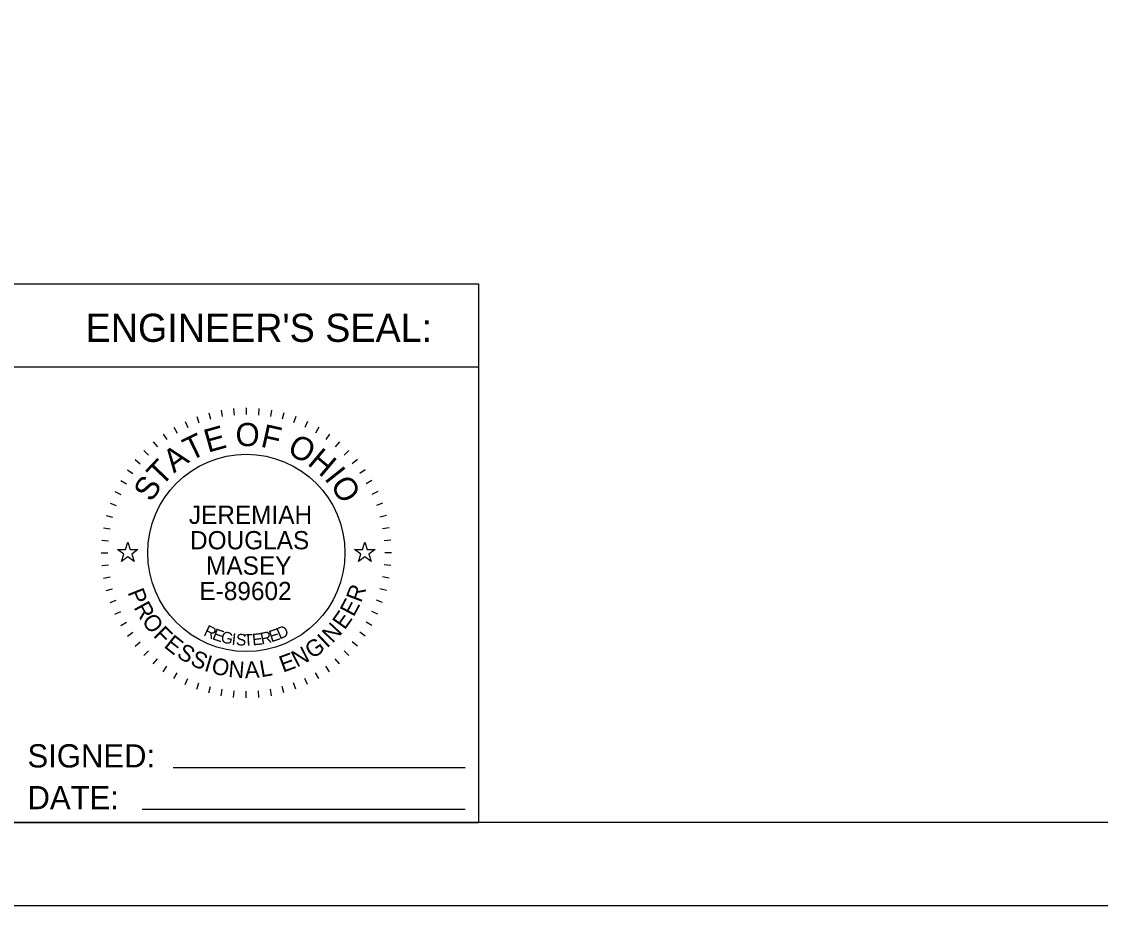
# Model space of a CAD drawing. Extents: x 0 to 36.5, y 0 to 25.3.
# Drawn here: x 23.3 to 29.81, y 0 to 5.33 of the extents above; entities that cross this region are included whole.
import ezdxf

# ---------------------------------------------------------------- set-up
doc = ezdxf.new("R2010")
doc.units = 0
for name, color, linetype in [('SH_Border', 7, 'Continuous'), ('SH_Cut_Line', 7, 'Continuous'), ('SH_Data', 7, 'Continuous'), ('SH_Text', 7, 'Continuous')]:
    doc.layers.add(name, color=color, linetype=linetype)

msp = doc.modelspace()

# ---------------------------------------------------------------- linework, layer by layer
at = {"layer": 'SH_Border'}
msp.add_lwpolyline([(1.5, 21.5), (33.5, 21.5), (33.5, 0.5), (1.5, 0.5)], close=True, dxfattribs=at)
at = {"layer": 'SH_Cut_Line'}
msp.add_lwpolyline([(0, 0), (34, 0), (34, 22), (0, 22)], close=True, dxfattribs=at)
at = {"layer": 'SH_Data'}
for p, q in [((23.2559, 3.75), (26.0559, 3.75)), ((23.2559, 3.25), (26.0559, 3.25)), ((24.5796, 2.9986), (24.5831, 2.9587)), ((24.6559, 3.0019), (24.6559, 2.9619)), ((24.7321, 2.9986), (24.7287, 2.9587)), ((24.3566, 2.9491), (24.3703, 2.9116)), ((24.4294, 2.9721), (24.4398, 2.9335)), ((24.5039, 2.9886), (24.5109, 2.9492)), ((24.8078, 2.9886), (24.8009, 2.9492)), ((24.8824, 2.9721), (24.872, 2.9335)), ((24.9552, 2.9491), (24.9415, 2.9116)), ((24.2184, 2.8847), (24.2384, 2.85)), ((24.2861, 2.9199), (24.303, 2.8837)), ((25.0257, 2.9199), (25.0088, 2.8837)), ((25.0934, 2.8847), (25.0734, 2.85)), ((24.154, 2.8437), (24.177, 2.8109)), ((25.1578, 2.8437), (25.1348, 2.8109)), ((24.0372, 2.7456), (24.0655, 2.7173)), ((24.0934, 2.7972), (24.1192, 2.7666)), ((25.2183, 2.7972), (25.1926, 2.7666)), ((25.2746, 2.7456), (25.2463, 2.7173)), ((23.9856, 2.6894), (24.0162, 2.6636)), ((25.3262, 2.6894), (25.2955, 2.6636)), ((23.9391, 2.6288), (23.9719, 2.6058)), ((25.3726, 2.6288), (25.3399, 2.6058)), ((23.8981, 2.5644), (23.9328, 2.5444)), ((25.4137, 2.5644), (25.379, 2.5444)), ((23.8629, 2.4967), (23.8991, 2.4798)), ((25.4489, 2.4967), (25.4127, 2.4798)), ((23.8337, 2.4262), (23.8712, 2.4125)), ((25.4781, 2.4262), (25.4405, 2.4125)), ((23.8107, 2.3534), (23.8493, 2.343)), ((25.5011, 2.3534), (25.4624, 2.343)), ((23.7942, 2.2789), (23.8336, 2.2719)), ((25.5176, 2.2789), (25.4782, 2.2719)), ((23.7842, 2.2032), (23.8241, 2.1997)), ((25.5276, 2.2032), (25.4877, 2.1997)), ((23.7809, 2.1269), (23.8209, 2.1269)), ((25.5309, 2.1269), (25.4909, 2.1269)), ((23.7842, 2.0507), (23.8241, 2.0541)), ((25.5276, 2.0507), (25.4877, 2.0541)), ((23.7942, 1.975), (23.8336, 1.9819)), ((25.5176, 1.975), (25.4782, 1.9819)), ((23.8107, 1.9004), (23.8493, 1.9108)), ((25.5011, 1.9004), (25.4624, 1.9108)), ((23.8337, 1.8276), (23.8712, 1.8413)), ((25.4781, 1.8276), (25.4405, 1.8413)), ((23.8629, 1.7571), (23.8991, 1.774)), ((25.4489, 1.7571), (25.4127, 1.774)), ((23.8981, 1.6894), (23.9328, 1.7094)), ((25.4137, 1.6894), (25.379, 1.7094)), ((23.9391, 1.625), (23.9719, 1.648)), ((25.3726, 1.625), (25.3399, 1.648)), ((23.9856, 1.5645), (24.0162, 1.5902)), ((25.3262, 1.5645), (25.2955, 1.5902)), ((24.0372, 1.5082), (24.0655, 1.5365)), ((25.2746, 1.5082), (25.2463, 1.5365)), ((24.0934, 1.4566), (24.1192, 1.4873)), ((24.154, 1.4102), (24.177, 1.4429)), ((25.1578, 1.4102), (25.1348, 1.4429)), ((25.2183, 1.4566), (25.1926, 1.4873)), ((24.2184, 1.3691), (24.2384, 1.4038)), ((24.2861, 1.3339), (24.303, 1.3701)), ((25.0257, 1.3339), (25.0088, 1.3701)), ((25.0934, 1.3691), (25.0734, 1.4038)), ((24.3566, 1.3047), (24.3703, 1.3423)), ((24.4294, 1.2817), (24.4398, 1.3204)), ((24.5039, 1.2652), (24.5109, 1.3046)), ((24.8078, 1.2652), (24.8009, 1.3046)), ((24.8824, 1.2817), (24.872, 1.3204)), ((24.9552, 1.3047), (24.9415, 1.3423)), ((24.5796, 1.2552), (24.5831, 1.2951)), ((24.6559, 1.2519), (24.6559, 1.2919)), ((24.7321, 1.2552), (24.7287, 1.2951)), ((23.2559, 0.5), (26.0559, 0.5))]:
    msp.add_line(p, q, dxfattribs=at)
msp.add_circle((24.6559, 2.1269), 0.595, dxfattribs=at)
at = {"layer": 'SH_Text'}
for p, q in [((26.0559, 3.75), (26.0559, 0.5)), ((24.2142, 0.8324), (25.9772, 0.8324)), ((24.028, 0.5805), (25.9772, 0.5805))]:
    msp.add_line(p, q, dxfattribs=at)
for points in [[(23.8795, 2.1469), (23.9264, 2.1469), (23.9409, 2.1914), (23.9554, 2.1469), (24.0023, 2.1469), (23.9644, 2.1193), (23.9789, 2.0747), (23.9409, 2.1023), (23.9029, 2.0747), (23.9174, 2.1193)], [(25.3095, 2.1469), (25.3564, 2.1469), (25.3709, 2.1914), (25.3854, 2.1469), (25.4323, 2.1469), (25.3944, 2.1193), (25.4089, 2.0747), (25.3709, 2.1023), (25.3329, 2.0747), (25.3474, 2.1193)]]:
    msp.add_lwpolyline(points, close=True, dxfattribs=at)

# ---------------------------------------------------------------- texts
at = {"layer": 'SH_Data'}
for s, height, rotation, p in [('E', 0.14, 15.75706, (24.4243, 2.7307)), ('O', 0.14, 359.78119, (24.5906, 2.7712)), ('F', 0.14, 347.43619, (24.7369, 2.7686)), ('T', 0.14, 25.71674, (24.3175, 2.6787)), ('O', 0.14, 332.25863, (24.8957, 2.7284)), ('A', 0.14, 36.47472, (24.2193, 2.605)), ('H', 0.14, 319.91363, (25.019, 2.663)), ('T', 0.14, 46.4344, (24.1442, 2.5234)), ('I', 0.14, 308.36695, (25.1223, 2.5752)), ('S', 0.14, 57.19238, (24.084, 2.4283)), ('O', 0.14, 303.14906, (25.158, 2.5358)), ('P', 0.1, 291.49398, (23.9382, 1.889)), ('R', 0.1, 69.23216, (25.3478, 1.8223)), ('R', 0.1, 298.73106, (23.9749, 1.7986)), ('E', 0.1, 61.99508, (25.3035, 1.7368)), ('E', 0.1, 54.75801, (25.2492, 1.6583)), ('O', 0.1, 306.46664, (24.0213, 1.7152)), ('N', 0.1, 47.02243, (25.1761, 1.5777)), ('F', 0.1, 314.7068, (24.0902, 1.6252)), ('E', 0.1, 321.43929, (24.1537, 1.5617)), ('R', 0.07, 334.48695, (24.3934, 1.632)), ('E', 0.07, 341.03996, (24.4465, 1.607)), ('G', 0.07, 347.47515, (24.4973, 1.5887)), ('I', 0.07, 353.78581, (24.565, 1.5737)), ('S', 0.07, 356.89262, (24.5917, 1.5698)), ('T', 0.07, 3.00609, (24.6416, 1.5656)), ('E', 0.07, 6.01169, (24.6948, 1.5681)), ('R', 0.07, 11.91844, (24.7484, 1.5743)), ('E', 0.07, 17.68363, (24.8057, 1.5871)), ('D', 0.07, 23.30524, (24.8569, 1.6039)), ('I', 0.1, 43.28703, (25.1427, 1.5483)), ('S', 0.1, 328.67637, (24.2302, 1.5021)), ('N', 0.1, 27.31129, (24.9604, 1.4344)), ('G', 0.1, 35.04687, (25.054, 1.4839)), ('S', 0.1, 335.91345, (24.3123, 1.4535)), ('I', 0.1, 343.15053, (24.3965, 1.4166)), ('E', 0.1, 20.07421, (24.8771, 1.4039)), ('O', 0.1, 346.88592, (24.4397, 1.4021)), ('N', 0.1, 355.12608, (24.5447, 1.3787)), ('A', 0.1, 2.86166, (24.6482, 1.3706)), ('L', 0.1, 10.09874, (24.7453, 1.376))]:
    msp.add_text(s, height=height, rotation=rotation, dxfattribs=at).set_placement(p)
for s, p in [('JEREMIAH', (24.3092, 2.3018)), ('DOUGLAS', (24.3163, 2.1486)), ('MASEY', (24.4132, 1.9953)), ('E-89602', (24.373, 1.842))]:
    msp.add_text(s, height=0.11, dxfattribs=at).set_placement(p)
at = {"layer": 'SH_Text'}
for s, height, p in [("ENGINEER'S SEAL:", 0.17, (23.6866, 3.4)), ('SIGNED:', 0.14, (23.3359, 0.8324)), ('DATE:', 0.14, (23.3359, 0.5805))]:
    msp.add_text(s, height=height, dxfattribs=at).set_placement(p)

doc.saveas('drawing.dxf')
